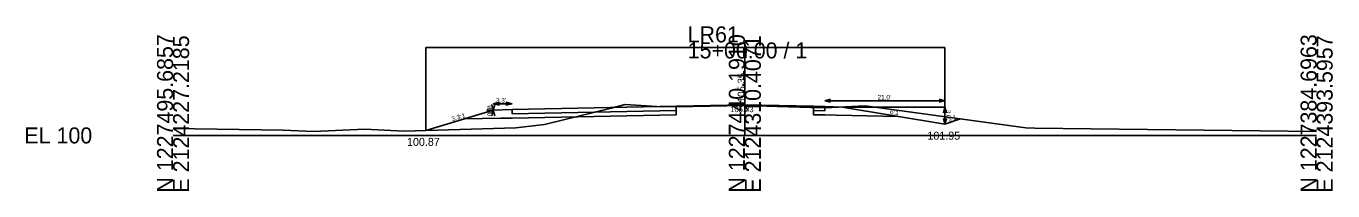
# Model space of a CAD drawing. Extents: x 2126751 to 2128979, y 1225108 to 1234639.
# Drawn here: x 2127750.9 to 2127979.4, y 1230107.5 to 1230136.3 of the extents above; entities that cross this region are included whole.
import ezdxf

# ---------------------------------------------------------------- set-up
doc = ezdxf.new("R2010")
doc.units = 0
for name, color, linetype in [('XS_CELL', 7, 'Continuous'), ('XS_M_DITCH', 7, 'Continuous'), ('XS_P_FINISHED_GRADE', 7, 'Continuous'), ('XS_P_FINISHED_GRADE_ELEV_TX', 7, 'Continuous'), ('XS_P_SUBGRADE_GRANULAR', 7, 'Continuous'), ('XS_P_SUBGRADE_LEVELING', 7, 'Continuous'), ('XS_P_SUBGRADE_PAVEMENT', 7, 'Continuous'), ('XS_P_TX_CLEARZONE', 7, 'Continuous'), ('XS_P_TX_DCH', 7, 'Continuous'), ('XS_P_TX_FS_BS', 7, 'Continuous'), ('XS_X_GROUND', 7, 'Continuous'), ('XS_X_GROUND_TX', 7, 'Continuous')]:
    doc.layers.add(name, color=color, linetype=linetype)

msp = doc.modelspace()

# ---------------------------------------------------------------- linework, layer by layer
at = {"layer": 'XS_CELL'}
for p, q in [((2127876.61, 1230117.21), (2127876.61, 1230133.47)), ((2127776.61, 1230117.21), (2127876.61, 1230117.21)), ((2127876.61, 1230117.21), (2127976.61, 1230117.21))]:
    msp.add_line(p, q, dxfattribs=at)
at = {"layer": 'XS_M_DITCH'}
for p, q in [((2127820.83, 1230118.08), (2127820.83, 1230132.56)), ((2127820.83, 1230132.56), (2127911.61, 1230132.56)), ((2127911.61, 1230132.56), (2127911.61, 1230119.16))]:
    msp.add_line(p, q, dxfattribs=at)
at = {"layer": 'XS_P_FINISHED_GRADE'}
for p, q in [((2127864.61, 1230122.32), (2127876.61, 1230122.56)), ((2127876.61, 1230122.56), (2127888.61, 1230122.32)), ((2127832.62, 1230121.63), (2127820.83, 1230118.08)), ((2127835.94, 1230121.75), (2127832.62, 1230121.63)), ((2127864.61, 1230122.32), (2127835.94, 1230121.75)), ((2127888.61, 1230122.32), (2127890.61, 1230122.28)), ((2127890.61, 1230122.28), (2127893.61, 1230122.16)), ((2127893.61, 1230122.16), (2127911.61, 1230119.16)), ((2127911.61, 1230119.16), (2127914.35, 1230120.08))]:
    msp.add_line(p, q, dxfattribs=at)
at = {"layer": 'XS_P_SUBGRADE_GRANULAR'}
for p, q in [((2127833.94, 1230120.21), (2127827.47, 1230120.08)), ((2127835.94, 1230120.25), (2127833.94, 1230120.21)), ((2127864.61, 1230120.82), (2127835.94, 1230120.25)), ((2127864.61, 1230120.82), (2127864.61, 1230121.57)), ((2127888.61, 1230120.82), (2127888.61, 1230121.57)), ((2127888.61, 1230120.82), (2127890.61, 1230120.78)), ((2127890.61, 1230120.78), (2127892.61, 1230120.74)), ((2127892.61, 1230120.74), (2127903.43, 1230120.53))]:
    msp.add_line(p, q, dxfattribs=at)
at = {"layer": 'XS_P_SUBGRADE_LEVELING'}
for p, q in [((2127867.43, 1230122.28), (2127876.51, 1230122.44)), ((2127876.51, 1230122.44), (2127888.14, 1230122.11)), ((2127864.61, 1230122.32), (2127864.61, 1230122.24)), ((2127864.61, 1230122.24), (2127867.43, 1230122.28)), ((2127888.14, 1230122.11), (2127888.61, 1230122.1)), ((2127888.61, 1230122.32), (2127888.61, 1230122.1))]:
    msp.add_line(p, q, dxfattribs=at)
at = {"layer": 'XS_P_SUBGRADE_PAVEMENT'}
for p, q in [((2127835.94, 1230121), (2127835.94, 1230121.75)), ((2127864.61, 1230121.57), (2127835.94, 1230121)), ((2127864.61, 1230121.57), (2127864.61, 1230122.24)), ((2127888.61, 1230121.57), (2127888.61, 1230122.1)), ((2127888.61, 1230121.57), (2127890.61, 1230121.53)), ((2127890.61, 1230121.53), (2127890.61, 1230122.28))]:
    msp.add_line(p, q, dxfattribs=at)
at = {"layer": 'XS_P_TX_CLEARZONE'}
for p, q in [((2127832.62, 1230121.63), (2127832.34, 1230122.63)), ((2127832.62, 1230122.75), (2127833.73, 1230123)), ((2127832.62, 1230122.75), (2127833.73, 1230122.5)), ((2127835.94, 1230122.75), (2127832.62, 1230122.75)), ((2127832.62, 1230121.63), (2127832.9, 1230122.63)), ((2127835.94, 1230122.75), (2127834.83, 1230123)), ((2127835.94, 1230122.75), (2127834.83, 1230122.5)), ((2127890.61, 1230123.28), (2127891.61, 1230123.53)), ((2127890.61, 1230123.28), (2127891.61, 1230123.03)), ((2127890.61, 1230123.28), (2127911.61, 1230123.28)), ((2127911.61, 1230123.28), (2127910.61, 1230123.53)), ((2127911.61, 1230123.28), (2127910.61, 1230123.03)), ((2127831.51, 1230121.63), (2127832.62, 1230121.63)), ((2127832.62, 1230121.63), (2127832.34, 1230120.63)), ((2127832.62, 1230121.63), (2127832.9, 1230120.63)), ((2127894.61, 1230122.16), (2127911.61, 1230122.16)), ((2127911.61, 1230122.16), (2127911.36, 1230121.16)), ((2127911.61, 1230119.16), (2127911.36, 1230120.16)), ((2127911.61, 1230122.16), (2127911.61, 1230119.16)), ((2127911.61, 1230122.16), (2127911.86, 1230121.16)), ((2127911.61, 1230119.16), (2127911.86, 1230120.16))]:
    msp.add_line(p, q, dxfattribs=at)
at = {"layer": 'XS_X_GROUND'}
for p, q in [((2127853.24, 1230121.99), (2127855.69, 1230122.63)), ((2127855.69, 1230122.63), (2127858.46, 1230122.45)), ((2127858.46, 1230122.45), (2127862.16, 1230122.2)), ((2127867.43, 1230122.28), (2127876.51, 1230122.44)), ((2127876.51, 1230122.44), (2127888.14, 1230122.11)), ((2127841.56, 1230119.14), (2127853.24, 1230121.99)), ((2127862.16, 1230122.2), (2127867.43, 1230122.28)), ((2127888.14, 1230122.11), (2127890.55, 1230122.04)), ((2127890.55, 1230122.04), (2127891.8, 1230122.09)), ((2127891.8, 1230122.09), (2127897.63, 1230122.36)), ((2127897.63, 1230122.36), (2127925.75, 1230118.52)), ((2127776.61, 1230118.4), (2127795.86, 1230118.13)), ((2127795.86, 1230118.13), (2127801.17, 1230117.92)), ((2127801.17, 1230117.92), (2127810.16, 1230118.29)), ((2127810.16, 1230118.29), (2127816.98, 1230117.97)), ((2127816.98, 1230117.97), (2127836.58, 1230118.55)), ((2127836.58, 1230118.55), (2127841.56, 1230119.14)), ((2127925.75, 1230118.52), (2127927.31, 1230118.5)), ((2127927.31, 1230118.5), (2127976.61, 1230117.87))]:
    msp.add_line(p, q, dxfattribs=at)

# ---------------------------------------------------------------- texts
at = {"layer": 'XS_CELL'}
for s, p in [('LR61', (2127866.61, 1230133.47)), ('15+00.00 / 1', (2127866.61, 1230130.67)), ('EL 100', (2127750.61, 1230115.81))]:
    msp.add_text(s, height=2.8, dxfattribs=at).set_placement(p)
for s, p in [('N 1227495.6857', (2127776.61, 1230107.21)), ('E 2124227.2185', (2127779.41, 1230107.21)), ('N 1227440.1910', (2127876.61, 1230107.21)), ('E 2124310.4071', (2127879.41, 1230107.21)), ('N 1227384.6963', (2127976.61, 1230107.21)), ('E 2124393.5957', (2127979.41, 1230107.21))]:
    msp.add_text(s, height=2.8, rotation=90, dxfattribs=at).set_placement(p)
at = {"layer": 'XS_P_FINISHED_GRADE_ELEV_TX'}
msp.add_text(' 105.35', height=1.25, rotation=90, dxfattribs=at).set_placement((2127876.61, 1230122.56))
at = {"layer": 'XS_P_TX_CLEARZONE'}
for s, p in [("3.3'", (2127833.1, 1230122.95)), ("21.0'", (2127899.82, 1230123.48))]:
    msp.add_text(s, height=0.8, dxfattribs=at).set_placement(p)
for s, rotation, p in [("0.0'", 90, (2127832.4, 1230120.57)), ("3.0'", 270, (2127911.81, 1230121.69))]:
    msp.add_text(s, height=0.8, rotation=rotation, dxfattribs=at).set_placement(p)
at = {"layer": 'XS_P_TX_DCH'}
for s, p in [('101.95', (2127908.54, 1230116.46)), ('100.87', (2127817.53, 1230115.38))]:
    msp.add_text(s, height=1.4, dxfattribs=at).set_placement(p)
at = {"layer": 'XS_P_TX_FS_BS'}
for s, rotation, p in [('3.3:1', 16.7444, (2127825.47, 1230119.69)), ('1:0', 90, (2127832.42, 1230120.91)), ('6:1', 350.5377, (2127901.95, 1230120.97)), ('3:1', 18.4349, (2127912.27, 1230119.59))]:
    msp.add_text(s, height=0.8, rotation=rotation, dxfattribs=at).set_placement(p)
at = {"layer": 'XS_X_GROUND_TX'}
msp.add_text('105.23', height=1, dxfattribs=at).set_placement((2127874.05, 1230121.28))

doc.saveas('drawing.dxf')
